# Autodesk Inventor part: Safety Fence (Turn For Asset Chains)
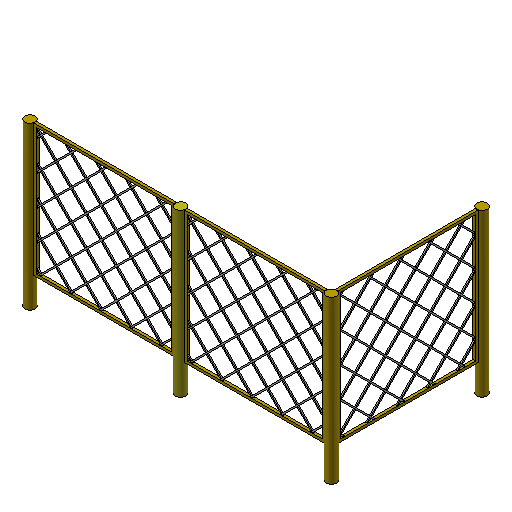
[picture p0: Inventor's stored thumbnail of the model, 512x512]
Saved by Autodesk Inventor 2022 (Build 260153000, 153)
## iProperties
ConnectorClass: SafetyEquipment
family_type: SafetyFence
Created: 2009-11
Part Number: Safety Fence (Turn For Asset Chains)
Document SubType Name: Modeling
Designer: Autodesk, Inc.
Density: 1 g/cm^3
Material: 一般
Appearance: 既定
Key Parameters: Height=1524.000 mm;BottomHeight=279.000 mm;Number=2.000 ul;TurnLength=1469.500 mm;SectionLength=2889.500 mm;Angle=90.00 deg
Author: Autodesk, Inc.
Title: Safety Fence (Turn For Asset Chains)
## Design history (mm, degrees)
sketch "Sketch1"
  geometry: L1 (0, -622.5)-(1321, -622.5); L2 (1321, -622.5)-(1321, 622.5); L3 (1321, 622.5)-(0, 622.5); L4 (0, 622.5)-(0, -622.5); L5 (25, -597.5)-(1296, -597.5); L6 (1296, -597.5)-(1296, 597.5); L7 (1296, 597.5)-(25, 597.5); L8 (25, 597.5)-(25, -597.5); 5 further points
  constraints: 16 end point, 4 midpoint, 4 parallel, 2 coincident, 2 horizontal, 2 perpendicular, 1 horizontal alignment, 1 vertical alignment
  dimensions: "d0" = 1245 distance of L3.end L1.start (= Height1); "d2" = 1321 distance of L1.start L1.end (= SectionLength_1); "d53" = 25 distance between parallel lines of L5 L1 (= WidthOfBranch); "d54" = 25 distance between parallel lines of L4 L8 (= WidthOfBranch)
extrude "Extrusion1" new body sketch "Sketch1" stored distance "d4" = 25.4; taper "d5" = 0 deg
sketch "Sketch2"
  geometry: L1 (50.4, 597.5)-(-1448.6, -901.5); L2 (68.361, 597.5)-(-1430.639, -901.5); L3 (-1448.6, -901.5)-(-1430.639, -901.5); L4 (50.4, 597.5)-(68.361, 597.5); L5 (25, 597.5)-(1296, 597.5) reference; L6 (25, -597.5)-(25, 597.5) reference; L7 (1296, 597.5)-(25, 597.5) reference; 2 further points
  constraints: 8 end point, 2 midpoint, 2 parallel, 1 horizontal alignment
  dimensions: "d10" = 12.7 distance between parallel lines of L1 L2; "d20" = 45 deg angle of L5 L1; "d21" = 25.4 distance from line of L6 L1.start; "d51" = 1499 distance between parallel lines of L4 L3 (derived)
extrude "Extrusion2" join sketch "Sketch2" stored distance "d7" = 12.7; taper "d8" = 0 deg
sketch "Sketch3"
  geometry: L1 (-1379.839, 883.539)-(101.2, -597.5); L2 (-1379.839, 901.5)-(119.161, -597.5); L3 (101.2, -597.5)-(119.161, -597.5); L4 (-1379.839, 883.539)-(-1379.839, 901.5); L5 (1296, -597.5)-(25, -597.5) reference; L6 (25, -597.5)-(25, 597.5) reference; 2 further points
  constraints: 8 end point, 2 midpoint, 1 horizontal alignment, 1 parallel, 1 perpendicular
  dimensions: "d13" = 12.7 distance between parallel lines of L1 L2; "d22" = 45 deg angle of L5 L1; "d23" = 76.2 distance of L5.end L1.end; "d24" = 1499 distance from line of L3 L2.start (derived)
extrude "Extrusion3" join sketch "Sketch3" stored distance "d14" = 12.7; taper "d15" = 0 deg
pattern_linear "Rectangular Pattern1" dims "d16" = 113.8 (derived), "d18" = 2845 (derived)
sketch "Sketch4"
  geometry: L1 (25, 597.5)-(25, -597.5) reference; L2 (25, -597.5)-(1296, -597.5) reference; L3 (1296, -597.5)-(1296, 597.5) reference; L4 (1296, 597.5)-(25, 597.5) reference; L5 (1321, -622.5)-(1321, 622.5) reference; L6 (0, -622.5)-(1321, -622.5) reference; L7 (0, 622.5)-(0, -622.5) reference; L8 (1321, 622.5)-(0, 622.5) reference; 1 further point
extrude "Extrusion4" sketch "Sketch4" stored distance "d25" = 127; taper "d26" = 0 deg
pattern_linear "Rectangular Pattern2" dims "d41" = 1420.06 (computed from SectionLength_1)
sketch "Sketch9" dims "d42" = 99 (= Diameter)
  geometry: L1 (0, 0)-(0, -25.4) reference; 3 further points
  constraints: 2 horizontal alignment, 1 midpoint, 2 other
extrude "Extrusion9" join sketch "Sketch9" stored distance "d97" = 12.7; taper "d98" = 0 deg
sketch "Sketch10"
  geometry: L1 (1321, -25.4)-(1321, 0) reference; C1 r 49.5 at (1370.5, -12.7); 1 further point
  constraints: 1 centre point, 1 horizontal alignment, 1 midpoint, 1 tangent
  dimensions: "d45" = 99 diameter of C1 (= Diameter)
extrude "Extrusion10" cut sketch "Sketch10" distance "d107" = 25.4; taper "d108" = 0 deg
workplane "Work Plane1"
  workaxis "Work Axis1"
sketch "Sketch15"
  geometry: L1 (1194.6, 74.5)-(1176.639, 74.5); L2 (2447.639, 1345.5)-(2465.6, 1345.5); L3 (2465.6, 1345.5)-(1194.6, 74.5); L4 (2447.639, 1345.5)-(1176.639, 74.5); L5 (50.4, 74.5)-(68.361, 74.5); L6 (68.361, 74.5)-(-1202.639, 1345.5); L7 (-1202.639, 1345.5)-(-1220.6, 1345.5); L8 (-1220.6, 1345.5)-(50.4, 74.5); 4 further points
  constraints: 16 end point, 5 parallel, 1 horizontal, 1 horizontal alignment, 1 midpoint
  dimensions: "d87" = 12.7 distance between parallel lines of L3 L4; "d88" = 25.4 distance of point (1220, 74.5) L1.start; "d89" = 1271 horizontal distance of L1.start L2.end (= TurnLength_1 - 2 x WidthOfBranch); "d90" = 45 deg angle of L1 L4; "d91" = 12.7 distance between parallel lines of L8 L6; "d92" = 25.4 distance of point (25, 74.5) L5.start; "d93" = 1271 horizontal distance of L5.start L7.end (= TurnLength_1 - 2 x WidthOfBranch); "d94" = 45 deg angle of L6 L5
workpoint "Work Point1"
  workaxis "Work Axis2"
workaxis "Work Axis3"
workpoint "Work Point2"
workplane "Work Plane5"
  workplane "Work Plane4"
workpoint "Work Point6"
node "Landing Surface"
node "Connector1"
workpoint "Work Point13"
  workaxis "Work Axis9"
  workplane "Work Plane12"
node "Connector2"
sketch "Sketch18"
  geometry: C1 r 49.5 at (0, 0) reference; 2 further points
  constraints: 1 coincident
workpoint "Work Point14"
node "Insertion Point1"
body "Solid1"
extrude "Extrusion5" join sketch "Sketch9" distance "d43" = 1524 (derived); taper "d44" = 0 deg
pattern_linear "Rectangular Pattern3" dims "d114" = 1420.06 (computed from SectionLength_1)
extrude "Extrusion6" join sketch "Sketch10" distance "d46" = 1524 (derived); taper "d47" = 0 deg
sketch "Sketch11"
  geometry: L1 (0, -49.5)-(0, 49.5) reference; L2 (0, 49.5)-(0, 1370.5); L3 (0, 1370.5)-(1245, 1370.5); L4 (1245, 1370.5)-(1245, 49.5); L5 (1245, 49.5)-(0, 49.5); L6 (25, 1345.5)-(25, 74.5); L7 (25, 74.5)-(1220, 74.5); L8 (1220, 74.5)-(1220, 1345.5); L9 (1220, 1345.5)-(25, 1345.5); 2 further points
  constraints: 16 end point, 4 parallel, 2 perpendicular, 1 collinear, 3 other
  dimensions: "d59" = 1321 distance of L1.end L2.end (= TurnLength_1); "d60" = 1245 distance of L4.end L1.end (= Height1); "d61" = 25 distance between parallel lines of L2 L6 (= WidthOfBranch)
extrude "Extrusion7" join sketch "Sketch11" stored distance "d62" = 25.4; taper "d63" = 0 deg
extrude "Extrusion8" join sketch "Sketch15" stored distance "d95" = 12.7; taper "d96" = 0 deg
pattern_linear "Rectangular Pattern4" dims "d99" = 113.8 (derived), "d101" = 2845 (derived)
pattern_linear "Rectangular Pattern5" dims "d102" = 113.8 (derived), "d104" = 2845 (derived)
sketch "Sketch17"
  geometry: L1 (0, 1321)-(-25.4, 1321) reference; C1 r 49.5 at (-12.7, 1370.5); 1 further point
  constraints: 1 centre point, 1 tangent
  dimensions: "d109" = 99 diameter of C1 (= Diameter)
extrude "Extrusion11" join sketch "Sketch17" distance "d110" = 1524 (derived); taper "d111" = 0 deg
node "Projected Loop1"
sketch "Sketch16"
  geometry: L1 (1370.5, 0)-(49.5, 0) reference; L2 (49.5, 1245)-(1370.5, 1245) reference; L3 (49.5, 0)-(49.5, -3963); L4 (49.5, -3963)-(1370.5, -3963); L5 (1370.5, -3963)-(1370.5, 0); L6 (1370.5, 1245)-(1370.5, 5208); L7 (1370.5, 5208)-(49.5, 5208); L8 (49.5, 5208)-(49.5, 1245)
  constraints: 12 end point, 3 equal length, 3 perpendicular
  dimensions: "d105" = 3963 distance of L4.end L1.start (derived); "d106" = 3963 distance of L2.end L6.end (= d105)
feature "Pattern of Solid1:15"
body "Solid16"
other parameters: "SectionLength_1" = 1321 [user parameter; used in 3 equation terms], "WidthOfBranch" = 25 [user parameter; used in 7 equation terms], "Diameter" = 99 [user parameter; used in 3 equation terms], "Height1" = 1245 [user parameter; used in 3 equation terms], "d52" = 90 deg (derived), "Angle_1" = 90 deg [user parameter], "TurnLength_1" = 1321 [user parameter; used in 3 equation terms], "d122" = -2840.12 (derived), "d149" = -1519.12, "d150" = 0, "d151" = 0, "d152" = -90 deg, "d153" = 0, "d154" = -180 deg, "d167" = 99 (derived), "d168" = 1370.5, "d169" = 0, "d170" = 1469.5, "d171" = -90 deg, "d172" = 0, "d173" = -90 deg
